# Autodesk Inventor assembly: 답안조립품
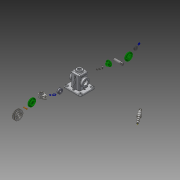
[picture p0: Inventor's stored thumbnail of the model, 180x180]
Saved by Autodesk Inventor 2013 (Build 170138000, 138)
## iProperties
Created: 2016-01
Part Number: 답안조립품
Document SubType Name: Assembly
Designer: User
Author: User
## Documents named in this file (19)
- C:\Users\User\Desktop\460126V1017\답안조립품.iam
- C:\Users\User\Desktop\460126V1017\V-벨트풀리.ipt
- C:\Users\User\Desktop\460126V1017\고정핀.ipt
- C:\Users\User\Desktop\460126V1017\뒤커버.ipt
- C:\Users\User\Desktop\460126V1017\링크.ipt
- C:\Users\User\Desktop\460126V1017\멈춤링 6 x 5.ipt
- C:\Users\User\Desktop\460126V1017\멈춤링 15 x 1.ipt
- C:\Users\User\Desktop\460126V1017\베어링 15 x 35 x 11.ipt
- C:\Users\User\Desktop\460126V1017\본체.ipt
- C:\Users\User\Desktop\460126V1017\볼트 M3 x 8.ipt
- C:\Users\User\Desktop\460126V1017\볼트 M4 x 10.ipt
- C:\Users\User\Desktop\460126V1017\볼트 M6 x 12.ipt
- C:\Users\User\Desktop\460126V1017\상부부시.ipt
- C:\Users\User\Desktop\460126V1017\슬라이드바.ipt
- C:\Users\User\Desktop\460126V1017\앞커버.ipt
- C:\Users\User\Desktop\460126V1017\오일실 15 25 7.ipt
- C:\Users\User\Desktop\460126V1017\와셔.ipt
- C:\Users\User\Desktop\460126V1017\키 5 x 5 x 14.ipt
- C:\Users\User\Desktop\460126V1017\편심축.ipt
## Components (5 placed, 5 different names)
1. V-벨트풀리:2
2. 고정핀:2
3. ISO 4762 M3 x 8:2
4. ISO 4762 M4 x 10:2
5. ISO 4018 M6 x 12:2
